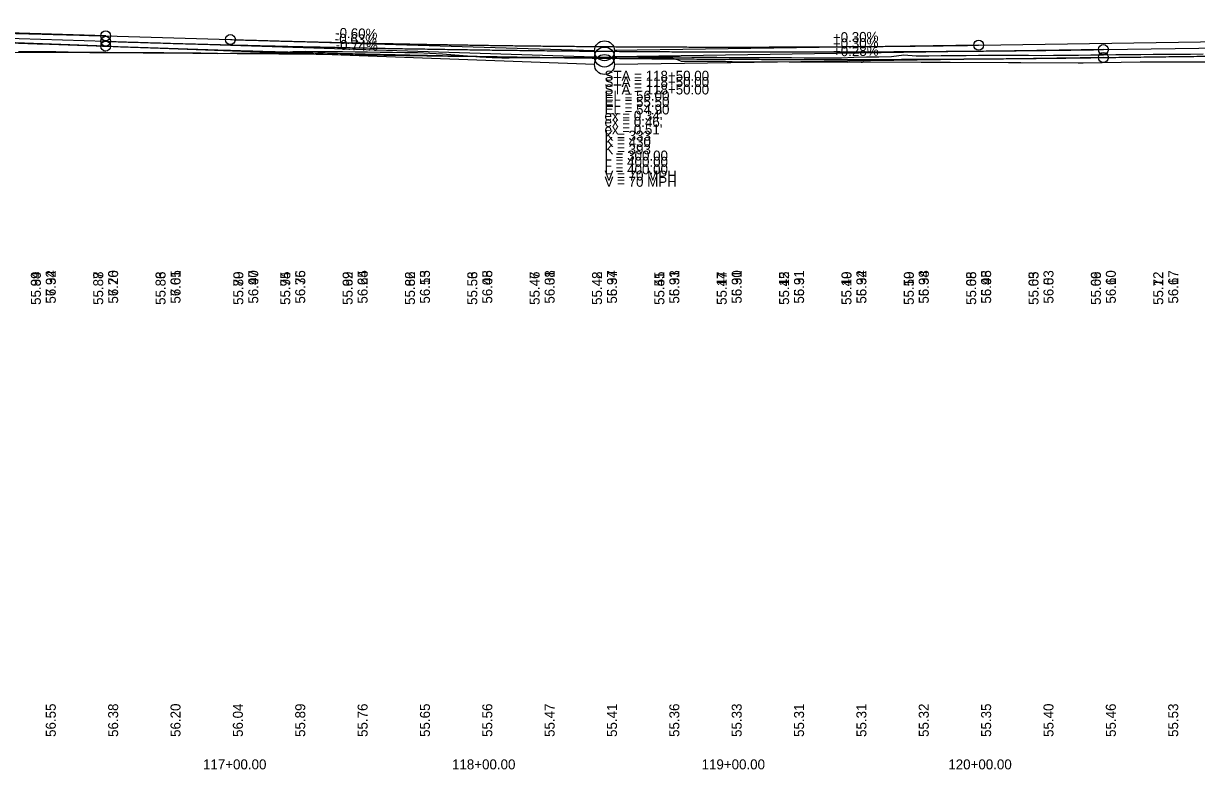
# Model space of a CAD drawing. Extents: x 3880794 to 3915434, y 287517 to 300173.
# Drawn here: x 3892155.3 to 3892625.7, y 296519.7 to 296818.7 of the extents above; entities that cross this region are included whole.
import ezdxf

# ---------------------------------------------------------------- set-up
doc = ezdxf.new("R2010")
doc.units = 0
for name, color, linetype in [('Level 1', 7, 'Continuous'), ('Level 2', 7, 'Continuous'), ('Level 30', 7, 'Continuous'), ('Level 31', 7, 'Continuous'), ('Level 32', 7, 'Continuous')]:
    doc.layers.add(name, color=color, linetype=linetype)

msp = doc.modelspace()

# ---------------------------------------------------------------- linework, layer by layer
at = {"layer": 'Level 1'}
for p, q in [((3892188.3, 296809.63), (3891942.29, 296818.71)), ((3892138.3, 296813.13), (3892188.3, 296811.56)), ((3892188.3, 296811.56), (3892384.3, 296805.38)), ((3892188.3, 296809.63), (3892384.3, 296802.4)), ((3892588.3, 296808.26), (3892392.3, 296805.32)), ((3892588.3, 296808.26), (3892638.3, 296809.01)), ((3892588.3, 296805.06), (3892834.3, 296808.5)), ((3892588.3, 296805.06), (3892392.3, 296802.31))]:
    msp.add_line(p, q, dxfattribs=at)
msp.add_lwpolyline([(3892138.13, 296806.96), (3892159.56, 296807.2), (3892162.57, 296807.2), (3892163.38, 296807.21), (3892181.96, 296807.11), (3892188.14, 296807.13), (3892206.37, 296807.13), (3892211.29, 296807.1), (3892211.6, 296807.1), (3892226.4, 296806.88), (3892233.14, 296806.78), (3892241.04, 296806.68), (3892257.66, 296806.54), (3892258.88, 296806.53), (3892264, 296806.52), (3892281.38, 296806.24), (3892287.48, 296806.2), (3892299.81, 296806.06), (3892300.54, 296806.05), (3892308.52, 296805.92), (3892325.48, 296805.65), (3892329, 296805.6), (3892336.71, 296805.65), (3892347.11, 296804.91), (3892348.59, 296804.92), (3892350.08, 296804.94), (3892359.41, 296805.11), (3892366.48, 296805.13), (3892374.99, 296804.89), (3892383.19, 296804.88), (3892390.78, 296804.83), (3892399.56, 296804.69), (3892406.75, 296805.12), (3892410.71, 296805.01), (3892412.77, 296805.03), (3892415.19, 296804.95), (3892417.79, 296804.14), (3892419.07, 296803.59), (3892435.42, 296803.63), (3892436.79, 296803.55), (3892437.45, 296803.51), (3892438.16, 296803.44), (3892439.43, 296803.49), (3892462.37, 296803.39), (3892463.84, 296803.36), (3892485.56, 296803.26), (3892486.44, 296803.27), (3892491.21, 296803.25), (3892491.74, 296803.24), (3892492.17, 296803.32), (3892515.21, 296803.24), (3892516.11, 296803.23), (3892517.02, 296803.22), (3892525.98, 296803.19), (3892526.84, 296803.19), (3892550.2, 296803.1), (3892551.66, 296803.09), (3892555.23, 296803.06), (3892578.21, 296802.91), (3892580.25, 296802.9), (3892603.04, 296803.34), (3892604.33, 296803.34), (3892615.26, 296803.35), (3892616.56, 296803.36), (3892639.44, 296803.38)], dxfattribs=at)
for centre in [(3892388.3, 296805.26), (3892388.3, 296802.26)]:
    msp.add_circle(centre, 4, dxfattribs=at)
for points in [[(3891688.3, 296815.27), (3891698.3, 296815.41), (3891708.3, 296815.54), (3891718.3, 296815.66), (3891728.3, 296815.77), (3891738.3, 296815.86), (3891748.3, 296815.95), (3891758.3, 296816.03), (3891768.3, 296816.09), (3891778.3, 296816.15), (3891788.3, 296816.19), (3891798.3, 296816.23), (3891808.3, 296816.26), (3891818.3, 296816.27), (3891828.3, 296816.28), (3891838.3, 296816.27), (3891848.3, 296816.26), (3891858.3, 296816.23), (3891868.3, 296816.19), (3891878.3, 296816.15), (3891888.3, 296816.09), (3891898.3, 296816.02), (3891908.3, 296815.95), (3891918.3, 296815.86), (3891928.3, 296815.76), (3891938.3, 296815.66), (3891948.3, 296815.54), (3891958.3, 296815.41), (3891968.3, 296815.27), (3891978.3, 296815.12), (3891988.3, 296814.96), (3891998.3, 296814.79), (3892008.3, 296814.62), (3892018.3, 296814.43), (3892028.3, 296814.23), (3892038.3, 296814.02), (3892048.3, 296813.8), (3892058.3, 296813.56), (3892068.3, 296813.32), (3892078.3, 296813.07), (3892088.3, 296812.81), (3892098.3, 296812.54), (3892108.3, 296812.26), (3892118.3, 296811.97), (3892128.3, 296811.66), (3892138.3, 296811.35), (3892148.3, 296811.03), (3892158.3, 296810.7), (3892168.3, 296810.35), (3892178.3, 296810), (3892188.3, 296809.63)], [(3892188.3, 296811.56), (3892196.3, 296811.31), (3892204.3, 296811.07), (3892212.3, 296810.83), (3892220.3, 296810.61), (3892228.3, 296810.39), (3892236.3, 296810.18), (3892244.3, 296809.98), (3892252.3, 296809.78), (3892260.3, 296809.59), (3892268.3, 296809.41), (3892276.3, 296809.24), (3892284.3, 296809.07), (3892292.3, 296808.91), (3892300.3, 296808.76), (3892308.3, 296808.61), (3892316.3, 296808.48), (3892324.3, 296808.35), (3892332.3, 296808.23), (3892340.3, 296808.11), (3892348.3, 296808), (3892356.3, 296807.91), (3892364.3, 296807.81), (3892372.3, 296807.73), (3892380.3, 296807.65), (3892388.3, 296807.58), (3892396.3, 296807.52), (3892404.3, 296807.46), (3892412.3, 296807.42), (3892420.3, 296807.38), (3892428.3, 296807.34), (3892436.3, 296807.32), (3892444.3, 296807.3), (3892452.3, 296807.29), (3892460.3, 296807.29), (3892468.3, 296807.29), (3892476.3, 296807.31), (3892484.3, 296807.33), (3892492.3, 296807.35), (3892500.3, 296807.39), (3892508.3, 296807.43), (3892516.3, 296807.48), (3892524.3, 296807.54), (3892532.3, 296807.6), (3892540.3, 296807.67), (3892548.3, 296807.75), (3892556.3, 296807.84), (3892564.3, 296807.93), (3892572.3, 296808.03), (3892580.3, 296808.14), (3892588.3, 296808.26)], [(3892188.3, 296809.63), (3892196.3, 296809.34), (3892204.3, 296809.06), (3892212.3, 296808.79), (3892220.3, 296808.52), (3892228.3, 296808.26), (3892236.3, 296808.01), (3892244.3, 296807.77), (3892252.3, 296807.53), (3892260.3, 296807.31), (3892268.3, 296807.09), (3892276.3, 296806.88), (3892284.3, 296806.68), (3892292.3, 296806.49), (3892300.3, 296806.3), (3892308.3, 296806.12), (3892316.3, 296805.96), (3892324.3, 296805.79), (3892332.3, 296805.64), (3892340.3, 296805.5), (3892348.3, 296805.36), (3892356.3, 296805.23), (3892364.3, 296805.11), (3892372.3, 296805), (3892380.3, 296804.9), (3892388.3, 296804.8), (3892396.3, 296804.71), (3892404.3, 296804.63), (3892412.3, 296804.56), (3892420.3, 296804.5), (3892428.3, 296804.45), (3892436.3, 296804.4), (3892444.3, 296804.36), (3892452.3, 296804.33), (3892460.3, 296804.31), (3892468.3, 296804.29), (3892476.3, 296804.29), (3892484.3, 296804.29), (3892492.3, 296804.3), (3892500.3, 296804.32), (3892508.3, 296804.34), (3892516.3, 296804.38), (3892524.3, 296804.42), (3892532.3, 296804.47), (3892540.3, 296804.53), (3892548.3, 296804.6), (3892556.3, 296804.67), (3892564.3, 296804.76), (3892572.3, 296804.85), (3892580.3, 296804.95), (3892588.3, 296805.06)], [(3892588.3, 296805.06), (3892598.3, 296805.19), (3892608.3, 296805.33), (3892618.3, 296805.45), (3892628.3, 296805.57), (3892638.3, 296805.69), (3892648.3, 296805.8), (3892658.3, 296805.9), (3892668.3, 296806), (3892678.3, 296806.09), (3892688.3, 296806.18), (3892698.3, 296806.26), (3892708.3, 296806.34), (3892718.3, 296806.41), (3892728.3, 296806.48), (3892738.3, 296806.54), (3892748.3, 296806.59), (3892758.3, 296806.64), (3892768.3, 296806.68), (3892778.3, 296806.72), (3892788.3, 296806.75), (3892798.3, 296806.78), (3892808.3, 296806.8), (3892818.3, 296806.81), (3892828.3, 296806.82), (3892838.3, 296806.83), (3892848.3, 296806.83), (3892858.3, 296806.82), (3892868.3, 296806.81), (3892878.3, 296806.79), (3892888.3, 296806.77), (3892898.3, 296806.74), (3892908.3, 296806.71), (3892918.3, 296806.67), (3892928.3, 296806.62), (3892938.3, 296806.57), (3892948.3, 296806.51), (3892958.3, 296806.45), (3892968.3, 296806.39), (3892978.3, 296806.31), (3892988.3, 296806.23), (3892998.3, 296806.15), (3893008.3, 296806.06), (3893018.3, 296805.97), (3893028.3, 296805.87), (3893038.3, 296805.76), (3893048.3, 296805.65), (3893058.3, 296805.53), (3893068.3, 296805.41), (3893078.3, 296805.28), (3893088.3, 296805.15)]]:
    msp.add_spline(points, degree=3, dxfattribs=at)
at = {"layer": 'Level 2'}
for p, q in [((3892188.3, 296813.76), (3892042.3, 296818.14)), ((3892188.3, 296813.76), (3892238.3, 296812.26)), ((3892238.3, 296812.26), (3892384.3, 296807.88)), ((3892538.3, 296810.01), (3892392.3, 296807.82)), ((3892538.3, 296810.01), (3892638.3, 296811.51))]:
    msp.add_line(p, q, dxfattribs=at)
for points in [[(3892153.3, 296807.47), (3892158.3, 296807.46), (3892163.3, 296807.44), (3892168.3, 296807.42), (3892173.3, 296807.32), (3892178.3, 296807.22), (3892183.3, 296807.19), (3892188.3, 296807.15), (3892193.3, 296807.11), (3892198.3, 296807.04), (3892203.3, 296806.98), (3892208.3, 296806.93), (3892213.3, 296806.92), (3892218.3, 296806.9), (3892223.3, 296806.84), (3892228.3, 296806.75), (3892233.3, 296806.7), (3892238.3, 296806.76), (3892243.3, 296806.79), (3892248.3, 296806.8), (3892253.3, 296806.78), (3892258.3, 296806.89), (3892263.3, 296807.47), (3892268.3, 296807.55), (3892273.3, 296807.51), (3892278.3, 296807.46), (3892283.3, 296807.42), (3892288.3, 296807.33), (3892293.3, 296807.32), (3892298.3, 296807.25), (3892303.3, 296807.17), (3892308.3, 296807.1), (3892313.3, 296807.05), (3892318.3, 296806.86), (3892323.3, 296806.57), (3892328.3, 296806.18), (3892333.3, 296805.79), (3892338.3, 296805.4), (3892343.3, 296805.1), (3892348.3, 296805.08), (3892353.3, 296805.06), (3892358.3, 296805.04), (3892363.3, 296805.03), (3892368.3, 296805.07), (3892373.3, 296805.1), (3892378.3, 296805.13), (3892383.3, 296805.16), (3892388.3, 296805.17), (3892393.3, 296805.22), (3892398.3, 296805.28), (3892403.3, 296805.33), (3892408.3, 296805.37), (3892413.3, 296805.33), (3892418.3, 296805.29), (3892423.3, 296805.25), (3892428.3, 296805.21), (3892433.3, 296805.17), (3892438.3, 296805.11), (3892443.3, 296805.1), (3892448.3, 296805.08), (3892453.3, 296805.07), (3892458.3, 296805.06), (3892463.3, 296805.02), (3892468.3, 296805), (3892473.3, 296804.99), (3892478.3, 296804.98), (3892483.3, 296804.96), (3892488.3, 296805.2), (3892493.3, 296805.34), (3892498.3, 296805.38), (3892503.3, 296805.42), (3892508.3, 296806.1), (3892513.3, 296805.71), (3892518.3, 296805.79), (3892523.3, 296805.83), (3892528.3, 296805.88), (3892533.3, 296805.93), (3892538.3, 296805.98)], [(3892538.3, 296805.98), (3892543.3, 296805.99), (3892548.3, 296805.99), (3892553.3, 296806), (3892558.3, 296805.99), (3892563.3, 296805.92), (3892568.3, 296805.96), (3892573.3, 296806), (3892578.3, 296806.05), (3892583.3, 296806.13), (3892588.3, 296806.18), (3892593.3, 296806.22), (3892598.3, 296806.25), (3892603.3, 296806.32), (3892608.3, 296806.37), (3892613.3, 296806.38), (3892618.3, 296806.4), (3892623.3, 296806.41), (3892628.3, 296806.49)]]:
    msp.add_lwpolyline(points, dxfattribs=at)
for centre, radius in [((3892188.3, 296813.76), 2), ((3892238.3, 296812.26), 2), ((3892388.3, 296807.76), 4), ((3892538.3, 296810.01), 2)]:
    msp.add_circle(centre, radius, dxfattribs=at)
for points in [[(3891888.3, 296816.01), (3891894.3, 296816.09), (3891900.3, 296816.18), (3891906.3, 296816.25), (3891912.3, 296816.32), (3891918.3, 296816.39), (3891924.3, 296816.45), (3891930.3, 296816.5), (3891936.3, 296816.55), (3891942.3, 296816.6), (3891948.3, 296816.64), (3891954.3, 296816.67), (3891960.3, 296816.7), (3891966.3, 296816.72), (3891972.3, 296816.74), (3891978.3, 296816.75), (3891984.3, 296816.76), (3891990.3, 296816.76), (3891996.3, 296816.75), (3892002.3, 296816.74), (3892008.3, 296816.73), (3892014.3, 296816.71), (3892020.3, 296816.68), (3892026.3, 296816.65), (3892032.3, 296816.61), (3892038.3, 296816.57), (3892044.3, 296816.52), (3892050.3, 296816.47), (3892056.3, 296816.41), (3892062.3, 296816.35), (3892068.3, 296816.28), (3892074.3, 296816.2), (3892080.3, 296816.12), (3892086.3, 296816.04), (3892092.3, 296815.95), (3892098.3, 296815.85), (3892104.3, 296815.75), (3892110.3, 296815.64), (3892116.3, 296815.53), (3892122.3, 296815.41), (3892128.3, 296815.29), (3892134.3, 296815.16), (3892140.3, 296815.02), (3892146.3, 296814.88), (3892152.3, 296814.74), (3892158.3, 296814.59), (3892164.3, 296814.43), (3892170.3, 296814.27), (3892176.3, 296814.11), (3892182.3, 296813.93), (3892188.3, 296813.76)], [(3892238.3, 296812.26), (3892244.3, 296812.08), (3892250.3, 296811.91), (3892256.3, 296811.74), (3892262.3, 296811.58), (3892268.3, 296811.42), (3892274.3, 296811.27), (3892280.3, 296811.13), (3892286.3, 296810.99), (3892292.3, 296810.86), (3892298.3, 296810.73), (3892304.3, 296810.6), (3892310.3, 296810.49), (3892316.3, 296810.37), (3892322.3, 296810.27), (3892328.3, 296810.16), (3892334.3, 296810.07), (3892340.3, 296809.98), (3892346.3, 296809.89), (3892352.3, 296809.81), (3892358.3, 296809.74), (3892364.3, 296809.67), (3892370.3, 296809.6), (3892376.3, 296809.55), (3892382.3, 296809.49), (3892388.3, 296809.44), (3892394.3, 296809.4), (3892400.3, 296809.37), (3892406.3, 296809.33), (3892412.3, 296809.31), (3892418.3, 296809.29), (3892424.3, 296809.27), (3892430.3, 296809.26), (3892436.3, 296809.26), (3892442.3, 296809.26), (3892448.3, 296809.26), (3892454.3, 296809.28), (3892460.3, 296809.29), (3892466.3, 296809.32), (3892472.3, 296809.34), (3892478.3, 296809.38), (3892484.3, 296809.42), (3892490.3, 296809.46), (3892496.3, 296809.51), (3892502.3, 296809.56), (3892508.3, 296809.62), (3892514.3, 296809.69), (3892520.3, 296809.76), (3892526.3, 296809.84), (3892532.3, 296809.92), (3892538.3, 296810.01)]]:
    msp.add_spline(points, degree=3, dxfattribs=at)
at = {"layer": 'Level 31'}
for centre in [(3892188.3, 296811.56), (3892188.3, 296809.63), (3892188.3, 296809.63), (3892588.3, 296808.26), (3892588.3, 296805.06), (3892588.3, 296805.06)]:
    msp.add_circle(centre, 2, dxfattribs=at)

# ---------------------------------------------------------------- texts
at = {"layer": 'Level 2'}
for s, rotation, p in [('-0.60%', 358.2816, (3892280.25, 296813)), ('+0.30%', 0.8594, (3892479.88, 296811.13)), ('57.34', 90, (3892168.3, 296706.43)), ('57.20', 90, (3892193.3, 296706.43)), ('57.05', 90, (3892218.3, 296706.43)), ('56.90', 90, (3892249.47, 296706.43)), ('56.76', 90, (3892268.3, 296706.43)), ('56.64', 90, (3892293.3, 296706.43)), ('56.53', 90, (3892318.3, 296706.43)), ('56.45', 90, (3892343.3, 296706.43)), ('56.38', 90, (3892368.3, 296706.43)), ('56.34', 90, (3892393.3, 296706.43)), ('56.31', 90, (3892418.3, 296706.43)), ('56.30', 90, (3892443.3, 296706.43)), ('56.31', 90, (3892468.3, 296706.43)), ('56.34', 90, (3892493.3, 296706.43)), ('56.38', 90, (3892518.3, 296706.43)), ('56.45', 90, (3892543.3, 296706.43)), ('56.53', 90, (3892568.3, 296706.43)), ('56.60', 90, (3892593.3, 296706.43)), ('56.67', 90, (3892618.3, 296706.43))]:
    msp.add_text(s, height=4, rotation=rotation, dxfattribs=at).set_placement(p)
for s, p in [('STA = 118+50.00', (3892388.3, 296795.76)), ('EL = 56.00', (3892388.3, 296787.76)), ("ex = 0.34'", (3892388.3, 296779.76)), ('K = 333', (3892388.3, 296771.76)), ('L = 300.00', (3892388.3, 296763.76)), ('V = 70 MPH', (3892388.3, 296755.76)), ('117+00.00', (3892227.31, 296519.76)), ('118+00.00', (3892327.15, 296519.76)), ('119+00.00', (3892427.21, 296519.76)), ('120+00.00', (3892526.14, 296519.76))]:
    msp.add_text(s, height=4, dxfattribs=at).set_placement(p)
at = {"layer": 'Level 30'}
for s, p in [('55.89', (3892162.3, 296705.91)), ('55.87', (3892187.3, 296705.91)), ('55.86', (3892212.3, 296705.91)), ('55.79', (3892243.47, 296705.91)), ('55.75', (3892262.3, 296705.91)), ('55.69', (3892287.3, 296705.91)), ('55.62', (3892312.3, 296705.91)), ('55.56', (3892337.3, 296705.91)), ('55.47', (3892362.3, 296705.91)), ('55.42', (3892387.3, 296705.91)), ('55.45', (3892412.3, 296705.91)), ('55.14', (3892437.3, 296705.91)), ('55.12', (3892462.3, 296705.91)), ('55.10', (3892487.3, 296705.91)), ('55.10', (3892512.3, 296705.91)), ('55.08', (3892537.3, 296705.91)), ('55.05', (3892562.3, 296705.91)), ('55.06', (3892587.3, 296705.91)), ('55.12', (3892612.3, 296705.91))]:
    msp.add_text(s, height=4, rotation=90, dxfattribs=at).set_placement(p)
for s, p in [('117+00.00', (3892227.31, 296519.76)), ('117+00.00', (3892227.31, 296519.76)), ('117+00.00', (3892227.31, 296519.76)), ('118+00.00', (3892327.15, 296519.76)), ('118+00.00', (3892327.15, 296519.76)), ('118+00.00', (3892327.15, 296519.76)), ('119+00.00', (3892427.21, 296519.76)), ('119+00.00', (3892427.21, 296519.76)), ('119+00.00', (3892427.21, 296519.76)), ('120+00.00', (3892526.14, 296519.76)), ('120+00.00', (3892526.14, 296519.76)), ('120+00.00', (3892526.14, 296519.76))]:
    msp.add_text(s, height=4, dxfattribs=at).set_placement(p)
at = {"layer": 'Level 31'}
for s, rotation, p in [('-0.63%', 358.1958, (3892280.1, 296810.67)), ('+0.30%', 0.8594, (3892479.88, 296808.63)), ('-0.74%', 357.8874, (3892280.44, 296808.24)), ('+0.28%', 0.8021, (3892479.92, 296805.54)), ('56.92', 90, (3892168.3, 296706.43)), ('56.76', 90, (3892193.3, 296706.43)), ('56.61', 90, (3892218.3, 296706.43)), ('56.47', 90, (3892249.47, 296706.43)), ('56.35', 90, (3892268.3, 296706.43)), ('56.25', 90, (3892293.3, 296706.43)), ('56.15', 90, (3892318.3, 296706.43)), ('56.08', 90, (3892343.3, 296706.43)), ('56.01', 90, (3892368.3, 296706.43)), ('55.97', 90, (3892393.3, 296706.43)), ('55.93', 90, (3892418.3, 296706.43)), ('55.91', 90, (3892443.3, 296706.43)), ('55.91', 90, (3892468.3, 296706.43)), ('55.92', 90, (3892493.3, 296706.43)), ('55.94', 90, (3892518.3, 296706.43)), ('55.98', 90, (3892543.3, 296706.43)), ('56.03', 90, (3892568.3, 296706.43)), ('56.10', 90, (3892593.3, 296706.43)), ('56.17', 90, (3892618.3, 296706.43)), ('56.55', 90, (3892168.3, 296532.76)), ('56.38', 90, (3892193.3, 296532.76)), ('56.20', 90, (3892218.3, 296532.76)), ('56.04', 90, (3892243.3, 296532.76)), ('55.89', 90, (3892268.3, 296532.76)), ('55.76', 90, (3892293.3, 296532.76)), ('55.65', 90, (3892318.3, 296532.76)), ('55.56', 90, (3892343.3, 296532.76)), ('55.47', 90, (3892368.3, 296532.76)), ('55.41', 90, (3892393.3, 296532.76)), ('55.36', 90, (3892418.3, 296532.76)), ('55.33', 90, (3892443.3, 296532.76)), ('55.31', 90, (3892468.3, 296532.76)), ('55.31', 90, (3892493.3, 296532.76)), ('55.32', 90, (3892518.3, 296532.76)), ('55.35', 90, (3892543.3, 296532.76)), ('55.40', 90, (3892568.3, 296532.76)), ('55.46', 90, (3892593.3, 296532.76)), ('55.53', 90, (3892618.3, 296532.76))]:
    msp.add_text(s, height=4, rotation=rotation, dxfattribs=at).set_placement(p)
for s, p in [('STA = 118+50.00', (3892388.3, 296793.26)), ('STA = 118+50.00', (3892388.3, 296790.26)), ('EL = 55.50', (3892388.3, 296785.26)), ('EL = 54.90', (3892388.3, 296782.26)), ("ex = 0.46'", (3892388.3, 296777.26)), ("ex = 0.51'", (3892388.3, 296774.26)), ('K = 430', (3892388.3, 296769.26)), ('K = 393', (3892388.3, 296766.26)), ('L = 400.00', (3892388.3, 296761.26)), ('L = 400.00', (3892388.3, 296758.26)), ('V = 70 MPH', (3892388.3, 296753.26))]:
    msp.add_text(s, height=4, dxfattribs=at).set_placement(p)
at = {"layer": 'Level 32'}
for s, p in [('55.94', (3892162.3, 296705.91)), ('55.88', (3892187.3, 296705.91)), ('55.83', (3892212.3, 296705.91)), ('55.80', (3892243.47, 296705.91)), ('55.94', (3892262.3, 296705.91)), ('55.92', (3892287.3, 296705.91)), ('55.86', (3892312.3, 296705.91)), ('55.53', (3892337.3, 296705.91)), ('55.46', (3892362.3, 296705.91)), ('55.48', (3892387.3, 296705.91)), ('55.51', (3892412.3, 296705.91)), ('55.47', (3892437.3, 296705.91)), ('55.45', (3892462.3, 296705.91)), ('55.49', (3892487.3, 296705.91)), ('55.59', (3892512.3, 296705.91)), ('55.65', (3892537.3, 296705.91)), ('55.63', (3892562.3, 296705.91)), ('55.69', (3892587.3, 296705.91)), ('55.72', (3892612.3, 296705.91))]:
    msp.add_text(s, height=4, rotation=90, dxfattribs=at).set_placement(p)

doc.saveas('drawing.dxf')
